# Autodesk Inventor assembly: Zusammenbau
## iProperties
Created: 2005-01
Part Number: Zusammenbau
Document SubType Name: Assembly
Designer: ap
Manufacturer: Standard
Standards Organization: Custom
Author: ap
